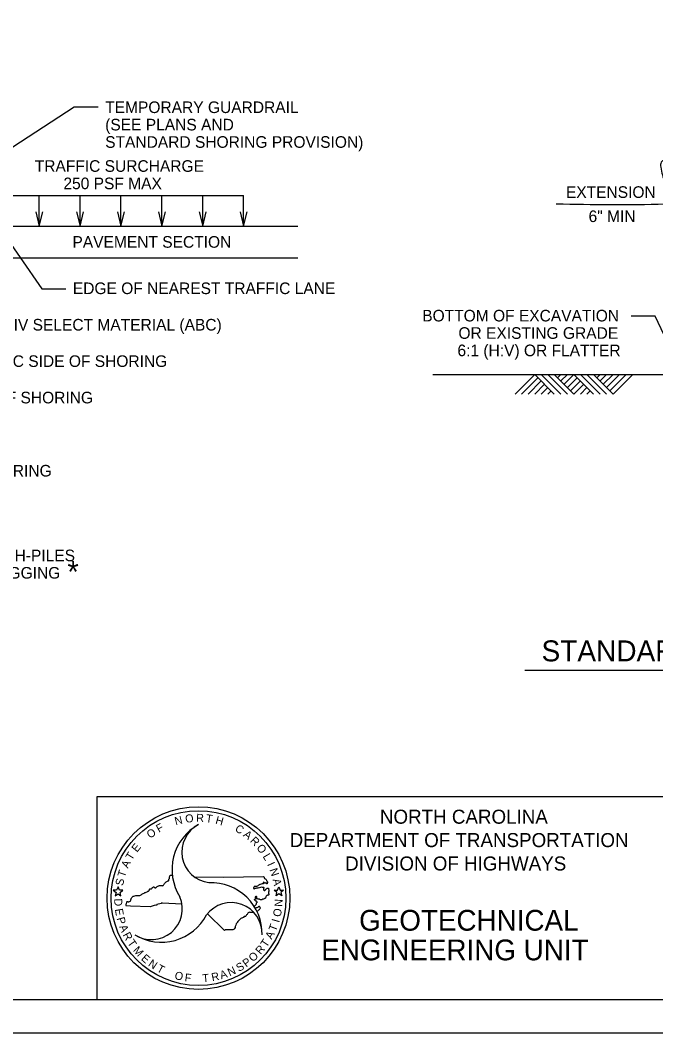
# Model space of a CAD drawing. Extents: x 1252282 to 1252638, y 733735 to 733845.
# Drawn here: x 1252571.3 to 1252608.4, y 733734.5 to 733793.6 of the extents above; entities that cross this region are included whole.
import ezdxf

# ---------------------------------------------------------------- set-up
doc = ezdxf.new("R2010")
doc.units = 0
for name, color, linetype in [('Default', 7, 'Continuous'), ('Sheet Plot Border Outside CELL', 7, 'Continuous'), ('Sheet Typical CELL', 7, 'Continuous')]:
    doc.layers.add(name, color=color, linetype=linetype)

msp = doc.modelspace()

# ---------------------------------------------------------------- linework, layer by layer
at = {"layer": 'Default'}
for p, q in [((1252567.007, 733783.693), (1252574.448, 733788.537)), ((1252574.448, 733788.537), (1252575.856, 733788.537)), ((1252570.021, 733783.365), (1252584.331, 733783.365)), ((1252572.406, 733781.576), (1252572.406, 733783.365)), ((1252574.791, 733781.576), (1252574.791, 733783.365)), ((1252577.176, 733781.576), (1252577.176, 733783.365)), ((1252579.561, 733781.576), (1252579.561, 733783.365)), ((1252581.946, 733781.576), (1252581.946, 733783.365)), ((1252584.331, 733781.576), (1252584.331, 733783.365)), ((1252565.675, 733781.576), (1252587.491, 733781.576)), ((1252570.021, 733781.576), (1252572.562, 733777.925)), ((1252565.675, 733779.735), (1252587.491, 733779.735)), ((1252572.562, 733777.925), (1252573.97, 733777.925)), ((1252595.38, 733772.922), (1252614.816, 733772.922)), ((1252600.171, 733771.778), (1252601.315, 733772.922)), ((1252601.315, 733772.922), (1252602.459, 733771.778)), ((1252601.696, 733772.922), (1252602.84, 733771.778)), ((1252602.077, 733772.922), (1252603.221, 733771.778)), ((1252602.459, 733772.922), (1252603.602, 733771.778)), ((1252602.649, 733772.731), (1252602.84, 733772.922)), ((1252602.84, 733772.54), (1252603.221, 733772.922)), ((1252603.03, 733772.35), (1252603.602, 733772.922)), ((1252603.602, 733772.922), (1252604.746, 733771.778)), ((1252603.984, 733772.922), (1252605.127, 733771.778)), ((1252604.365, 733772.922), (1252605.508, 733771.778)), ((1252604.746, 733772.922), (1252605.89, 733771.778)), ((1252604.936, 733772.731), (1252605.127, 733772.922)), ((1252605.127, 733772.54), (1252605.508, 733772.922)), ((1252605.318, 733772.35), (1252605.89, 733772.922)), ((1252605.508, 733772.159), (1252606.271, 733772.922)), ((1252605.699, 733771.969), (1252606.652, 733772.922)), ((1252605.89, 733771.778), (1252607.033, 733772.922)), ((1252600.552, 733771.778), (1252601.506, 733772.731)), ((1252600.934, 733771.778), (1252601.696, 733772.54)), ((1252601.315, 733771.778), (1252601.887, 733772.35)), ((1252603.221, 733772.159), (1252603.793, 733772.731)), ((1252603.412, 733771.969), (1252603.984, 733772.54)), ((1252603.602, 733771.778), (1252604.174, 733772.35)), ((1252601.696, 733771.778), (1252602.077, 733772.159)), ((1252602.077, 733771.778), (1252602.268, 733771.969)), ((1252603.984, 733771.778), (1252604.365, 733772.159)), ((1252604.365, 733771.778), (1252604.555, 733771.969)), ((1252600.744, 733755.669), (1252629.595, 733755.669)), ((1252580.053, 733743.695), (1252580.174, 733743.696)), ((1252581.477, 733743.608), (1252583.15, 733743.59)), ((1252583.15, 733743.59), (1252585.497, 733743.627)), ((1252579.559, 733742.082), (1252579.532, 733742.044)), ((1252579.599, 733742.064), (1252579.559, 733742.082)), ((1252577.735, 733741.882), (1252577.466, 733741.9)), ((1252578.876, 733741.85), (1252577.735, 733741.882)), ((1252579.173, 733741.942), (1252578.876, 733741.85)), ((1252579.25, 733741.929), (1252579.173, 733741.942)), ((1252579.269, 733741.979), (1252579.25, 733741.929)), ((1252579.532, 733742.044), (1252579.269, 733741.979)), ((1252580.738, 733742.002), (1252579.599, 733742.064)), ((1252583.213, 733740.477), (1252582.23, 733741.451))]:
    msp.add_line(p, q, dxfattribs=at)
for points in [[(1252572.204, 733782.412), (1252572.406, 733781.576), (1252572.617, 733782.412)], [(1252574.589, 733782.412), (1252574.791, 733781.576), (1252575.002, 733782.412)], [(1252576.974, 733782.412), (1252577.176, 733781.576), (1252577.387, 733782.412)], [(1252579.359, 733782.412), (1252579.561, 733781.576), (1252579.772, 733782.412)], [(1252581.744, 733782.412), (1252581.946, 733781.576), (1252582.157, 733782.412)], [(1252584.129, 733782.412), (1252584.331, 733781.576), (1252584.542, 733782.412)], [(1252609.957, 733772.922), (1252608.347, 733776.329), (1252606.939, 733776.329)]]:
    msp.add_lwpolyline(points, dxfattribs=at)
for points in [[(1252577.007, 733743.023), (1252576.925, 733742.815), (1252576.731, 733742.815), (1252576.891, 733742.686), (1252576.84, 733742.488), (1252577.006, 733742.614), (1252577.174, 733742.488), (1252577.124, 733742.686), (1252577.284, 733742.815), (1252577.09, 733742.815)], [(1252586.393, 733743.023), (1252586.475, 733742.815), (1252586.669, 733742.815), (1252586.509, 733742.686), (1252586.56, 733742.488), (1252586.394, 733742.614), (1252586.226, 733742.488), (1252586.276, 733742.686), (1252586.116, 733742.815), (1252586.31, 733742.815)]]:
    msp.add_lwpolyline(points, close=True, dxfattribs=at)
for radius in [5.329, 5.099]:
    msp.add_circle((1252581.7, 733742.36), radius, dxfattribs=at)
for centre, radius, start, end in [((1252583.145, 733744.032), 2.99, 118.8941, 212.22691), ((1252582.53, 733745.049), 1.801, 117.39309, 262.95143), ((1252582.425, 733740.273), 2.99, 358.89409, 92.2269), ((1252578.957, 733741.735), 1.801, 237.37927, 22.95866), ((1252583.613, 733740.298), 1.801, 357.39384, 142.94154), ((1252579.53, 733742.776), 2.99, 238.8941, 332.22691)]:
    msp.add_arc(centre, radius, start, end, dxfattribs=at)
for points in [[(1252611.825, 733785.416), (1252608.905, 733785.416), (1252608.867, 733785.415), (1252608.833, 733785.409), (1252608.776, 733785.388), (1252608.698, 733785.306), (1252608.668, 733785.017), (1252608.905, 733784.137), (1252609.142, 733783.258), (1252609.112, 733782.968), (1252609.035, 733782.887), (1252608.977, 733782.865), (1252608.943, 733782.86), (1252608.905, 733782.858), (1252602.574, 733782.858)], [(1252577.466, 733741.9), (1252577.485, 733741.973), (1252577.498, 733742.04), (1252577.519, 733742.1), (1252577.542, 733742.165), (1252577.567, 733742.16), (1252577.617, 733742.146), (1252577.661, 733742.154), (1252577.706, 733742.172), (1252577.742, 733742.206), (1252577.763, 733742.276), (1252577.769, 733742.334), (1252577.806, 733742.391), (1252577.887, 733742.466), (1252577.982, 733742.492), (1252578.096, 733742.51), (1252578.222, 733742.508), (1252578.316, 733742.528), (1252578.4, 733742.585), (1252578.482, 733742.628), (1252578.568, 733742.678), (1252578.656, 733742.697), (1252578.745, 733742.756), (1252578.809, 733742.792), (1252578.832, 733742.832), (1252578.845, 733742.871), (1252578.855, 733742.901), (1252578.884, 733742.906), (1252578.932, 733742.892), (1252578.982, 733742.93), (1252578.998, 733742.961), (1252579.048, 733742.997), (1252579.087, 733743.015), (1252579.112, 733743.007), (1252579.137, 733742.97), (1252579.161, 733742.95), (1252579.194, 733742.96), (1252579.24, 733742.979), (1252579.263, 733743.016), (1252579.331, 733743.062), (1252579.388, 733743.084), (1252579.469, 733743.102), (1252579.539, 733743.1), (1252579.568, 733743.09), (1252579.621, 733743.088), (1252579.651, 733743.115), (1252579.705, 733743.179), (1252579.741, 733743.23), (1252579.819, 733743.312), (1252579.884, 733743.348), (1252579.917, 733743.359), (1252579.957, 733743.373), (1252579.965, 733743.413), (1252579.974, 733743.443), (1252579.984, 733743.474), (1252580.01, 733743.511), (1252580.009, 733743.539), (1252580.009, 733743.596), (1252580.056, 733743.694)], [(1252585.497, 733743.627), (1252585.499, 733743.62), (1252585.529, 733743.577), (1252585.539, 733743.538), (1252585.594, 733743.489), (1252585.636, 733743.465), (1252585.664, 733743.408), (1252585.693, 733743.366), (1252585.72, 733743.247), (1252585.694, 733743.219), (1252585.706, 733743.201), (1252585.67, 733743.207), (1252585.656, 733743.246), (1252585.592, 733743.241), (1252585.541, 733743.25), (1252585.503, 733743.281), (1252585.47, 733743.27), (1252585.488, 733743.225), (1252585.475, 733743.196), (1252585.416, 733743.185), (1252585.3, 733743.158), (1252585.244, 733743.142), (1252585.189, 733743.098), (1252585.092, 733743.03), (1252585.031, 733743.042), (1252584.976, 733743.035), (1252584.956, 733743.039), (1252584.934, 733743.001), (1252584.91, 733742.954), (1252584.906, 733742.929), (1252584.928, 733742.911), (1252584.987, 733742.917), (1252585.074, 733742.949), (1252585.128, 733742.961), (1252585.234, 733742.97), (1252585.283, 733742.97), (1252585.374, 733743.012), (1252585.461, 733742.997), (1252585.506, 733742.987), (1252585.519, 733742.957), (1252585.501, 733742.918), (1252585.488, 733742.878), (1252585.498, 733742.845), (1252585.534, 733742.806), (1252585.589, 733742.819), (1252585.611, 733742.857), (1252585.662, 733742.906), (1252585.711, 733742.947), (1252585.749, 733742.945), (1252585.779, 733742.933), (1252585.79, 733742.883), (1252585.811, 733742.816), (1252585.799, 733742.751), (1252585.792, 733742.682), (1252585.793, 733742.635), (1252585.807, 733742.573), (1252585.797, 733742.544), (1252585.758, 733742.529), (1252585.711, 733742.513), (1252585.676, 733742.492), (1252585.657, 733742.474), (1252585.62, 733742.406), (1252585.602, 733742.362), (1252585.554, 733742.333), (1252585.496, 733742.305), (1252585.429, 733742.291)], [(1252585.429, 733742.291), (1252585.348, 733742.255), (1252585.278, 733742.273), (1252585.225, 733742.299), (1252585.195, 733742.301), (1252585.151, 733742.328), (1252585.13, 733742.305), (1252585.11, 733742.308), (1252585.102, 733742.352), (1252585.097, 733742.384), (1252585.103, 733742.42), (1252585.082, 733742.451), (1252585.048, 733742.467), (1252585.02, 733742.451), (1252585.015, 733742.394), (1252585.019, 733742.355), (1252585.015, 733742.309), (1252584.987, 733742.272), (1252584.97, 733742.291), (1252585.004, 733742.216), (1252585.065, 733742.2), (1252585.115, 733742.116), (1252585.079, 733742.081), (1252585.056, 733742.047), (1252585.068, 733742.025), (1252585.079, 733742.001), (1252585.042, 733741.967), (1252585.022, 733741.943), (1252584.959, 733741.885), (1252584.95, 733741.878)], [(1252584.92, 733741.538), (1252584.895, 733741.536), (1252584.823, 733741.513), (1252584.714, 733741.527), (1252584.633, 733741.523), (1252584.577, 733741.475), (1252584.535, 733741.413), (1252584.482, 733741.349), (1252584.435, 733741.292), (1252584.397, 733741.294), (1252584.365, 733741.289), (1252584.354, 733741.259), (1252584.368, 733741.247), (1252584.312, 733741.23), (1252584.237, 733741.196), (1252584.165, 733741.166), (1252584.114, 733741.112), (1252584.045, 733741.054), (1252583.961, 733740.94), (1252583.904, 733740.849), (1252583.85, 733740.695), (1252583.807, 733740.586), (1252583.75, 733740.533), (1252583.65, 733740.504), (1252583.586, 733740.504), (1252583.462, 733740.515), (1252583.36, 733740.51), (1252583.264, 733740.506), (1252583.213, 733740.477)], [(1252585.119, 733741.575), (1252585.153, 733741.608), (1252585.223, 733741.669), (1252585.309, 733741.799), (1252585.288, 733741.838), (1252585.252, 733741.866), (1252585.219, 733741.887), (1252585.182, 733741.835), (1252585.107, 733741.8), (1252585.011, 733741.779)]]:
    msp.add_spline(points, degree=3, dxfattribs=at)
at = {"layer": 'Sheet Plot Border Outside CELL'}
msp.add_lwpolyline([(1252467.333, 733734.502), (1252637.975, 733734.502), (1252637.975, 733844.502), (1252467.333, 733844.502)], close=True, dxfattribs=at)
at = {"layer": 'Sheet Typical CELL'}
for points in [[(1252484.62, 733842.575), (1252636.257, 733842.575), (1252636.257, 733736.429), (1252484.62, 733736.429)], [(1252575.799, 733748.291), (1252636.257, 733748.291), (1252636.257, 733736.429), (1252575.799, 733736.429)]]:
    msp.add_lwpolyline(points, close=True, dxfattribs=at)

# ---------------------------------------------------------------- texts
at = {"layer": 'Default'}
for s, height, p in [('TEMPORARY GUARDRAIL', 0.67788, (1252576.258, 733788.175)), ('(SEE PLANS AND', 0.67788, (1252576.258, 733787.161)), ('STANDARD SHORING PROVISION)', 0.67788, (1252576.258, 733786.147)), ('TRAFFIC SURCHARGE', 0.67788, (1252572.148, 733784.745)), ('250 PSF MAX', 0.67788, (1252573.821, 733783.731)), ('EXTENSION', 0.6779, (1252603.135, 733783.224)), ('6" MIN', 0.6779, (1252604.458, 733781.814)), ('PAVEMENT SECTION', 0.67788, (1252574.348, 733780.316)), ('EDGE OF NEAREST TRAFFIC LANE', 0.67788, (1252574.371, 733777.609)), ('BOTTOM OF EXCAVATION', 0.67788, (1252594.753, 733776.013)), ('CLASS IV SELECT MATERIAL (ABC)', 0.67788, (1252567.692, 733775.483)), ('OR EXISTING GRADE', 0.67788, (1252596.866, 733774.999)), ('6:1 (H:V) OR FLATTER', 0.67788, (1252596.808, 733773.985)), ('TRAFFIC SIDE OF SHORING', 0.67788, (1252567.692, 733773.358)), ('TOP OF SHORING', 0.67788, (1252567.692, 733771.232)), ('BOTTOM OF SHORING', 0.67788, (1252563.265, 733766.963)), ('SHEET PILES OR H-PILES', 0.67788, (1252563.265, 733762.019)), ('WITH TIMBER LAGGING', 0.67788, (1252563.265, 733761.005)), ('*', 1.271, (1252574.053, 733760.771)), ('STANDARD TEMPORARY SHORING', 1.22323, (1252601.712, 733756.176)), ('NORTH CAROLINA', 0.81884, (1252592.285, 733746.701)), ('DEPARTMENT OF TRANSPORTATION', 0.81884, (1252587.019, 733745.336)), ('DIVISION OF HIGHWAYS', 0.81884, (1252590.257, 733743.971)), ('GEOTECHNICAL', 1.2131, (1252591.071, 733740.459)), ('ENGINEERING UNIT', 1.2131, (1252588.864, 733738.729))]:
    msp.add_text(s, height=height, dxfattribs=at).set_placement(p)
for s, rotation, p in [('N', 14.23018, (1252580.371, 733746.613)), ('O', 6.51157, (1252580.953, 733746.753)), ('R', 359.04997, (1252581.566, 733746.813)), ('T', 351.93748, (1252582.104, 733746.797)), ('H', 344.2742, (1252582.655, 733746.712)), ('O', 35.99769, (1252578.883, 733745.813)), ('F', 28.90791, (1252579.387, 733746.168)), ('C', 329.1439, (1252583.788, 733746.296)), ('A', 322.03527, (1252584.275, 733745.996)), ('R', 315.18315, (1252584.68, 733745.673)), ('T', 57.98026, (1252577.809, 733744.531)), ('E', 50.97363, (1252578.11, 733745)), ('O', 307.86363, (1252585.057, 733745.289)), ('A', 64.9935, (1252577.584, 733744.064)), ('L', 300.35163, (1252585.43, 733744.798)), ('I', 294.7935, (1252585.694, 733744.334)), ('T', 71.92177, (1252577.403, 733743.538)), ('N', 288.76221, (1252585.835, 733744.017)), ('S', 78.39292, (1252577.298, 733743.054)), ('A', 281.69841, (1252586.02, 733743.447)), ('D', 273.27152, (1252576.777, 733742.326)), ('N', 86.87198, (1252586.597, 733741.844)), ('E', 279.94138, (1252576.821, 733741.711)), ('O', 79.7125, (1252586.492, 733741.237)), ('P', 285.98116, (1252576.921, 733741.18)), ('I', 73.99616, (1252586.402, 733740.901)), ('A', 291.93563, (1252577.067, 733740.699)), ('R', 298.15995, (1252577.267, 733740.221)), ('A', 62.7344, (1252585.974, 733739.917)), ('T', 68.91429, (1252586.207, 733740.379)), ('T', 304.59872, (1252577.527, 733739.75)), ('T', 56.44299, (1252585.671, 733739.449)), ('M', 311.82373, (1252577.848, 733739.294)), ('O', 43.21042, (1252584.884, 733738.607)), ('R', 50.0395, (1252585.329, 733739.033)), ('E', 318.97657, (1252578.317, 733738.784)), ('N', 325.71433, (1252578.73, 733738.435)), ('S', 30.67055, (1252584.063, 733738.042)), ('P', 36.45523, (1252584.484, 733738.301)), ('T', 332.57441, (1252579.228, 733738.102)), ('O', 346.04003, (1252580.273, 733737.649)), ('F', 352.5633, (1252580.873, 733737.507)), ('T', 5.66027, (1252581.951, 733737.443)), ('R', 11.91909, (1252582.505, 733737.503)), ('A', 18.01861, (1252583.03, 733737.621)), ('N', 24.45258, (1252583.521, 733737.787))]:
    msp.add_text(s, height=0.467, rotation=rotation, dxfattribs=at).set_placement(p)

doc.saveas('drawing.dxf')
